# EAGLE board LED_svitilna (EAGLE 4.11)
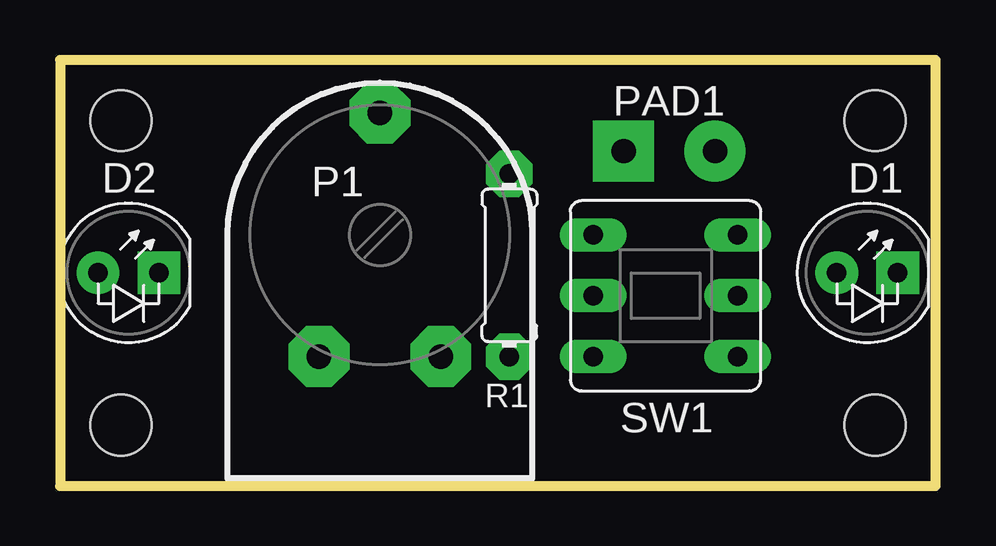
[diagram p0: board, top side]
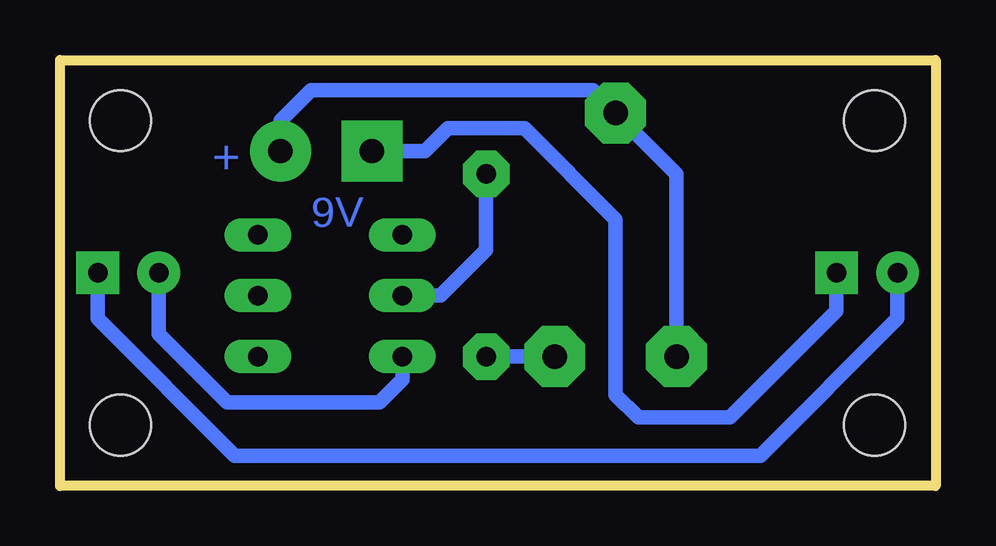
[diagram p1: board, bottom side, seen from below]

Size 36.5 x 17.77 mm. Coordinates in mm from the lower left corner, seen from the top.
Outline: 0,0 36.5,0 36.5,17.77 0,17.77 0,0
Copper layers (1*16): Top 0.035mm / dielectric 1.5mm / Bottom 0.035mm
Design rules "default": minimum track width 10mil, minimum drill 24mil, track to track 8mil, track to pad 8mil, pad to pad 8mil, via to via 8mil, smd to smd 8mil, copper to edge 40mil, drill to drill 8mil, minimum pad ring 10mil, minimum via ring 8mil, stop-mask expansion 4mil, vias tented up to drill 0mil, thermal gap 10mil
Holes 2.54 mm at 2.54,15.24 2.54,2.54 33.97,2.54 33.97,15.24

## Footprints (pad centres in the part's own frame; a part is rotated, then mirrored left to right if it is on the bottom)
LED_5 = drill 0.813 pad 1.778 round: A -1.27,0 | drill 0.813 pad 1.778 square: K 1.27,0
TP012 = drill 1.016 pad 2.54 octagon: 1 -2.54,-5.08; 2 0,5.08; 3 2.54,-5.08
PAD_2+- = drill 1.016 pad 2.54 round: + -1.905,0 | drill 1.016 pad 2.54 square: - 1.905,0
R-7,5 = drill 0.813 pad 1.93 octagon: 1 -3.81,0; 2 3.81,0
P-B170 = drill 0.813 pad 1.4 long: 1 0,5.08; 2 0,2.54; 3 0,0; 4 6.032,0; 5 6.032,2.54; 6 6.032,5.08

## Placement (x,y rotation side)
D1  LED_5  [LED_5]  33.66,8.89 0 top
D2  LED_5  [LED_5]  2.86,8.89 0 top
P1  [TP012]  13.34,10.48 0 top
PAD1  PAD_2+-  [PAD_2+-]  25.4,13.97 180 top
R1  [R-7,5]  18.73,9.21 270 top
SW1  P-B170  [P-B170]  22.23,5.4 0 top

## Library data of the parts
D1 D2 P1 PAD1 R1 SW1 = #PaJa_14

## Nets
N$1: P1.1 P1.2 PAD1.+
N$2: P1.3 R1.2
N$5: D1.K D2.A
N$6: D2.K PAD1.-
S$1: R1.1 SW1.2
S$2: D1.A SW1.3

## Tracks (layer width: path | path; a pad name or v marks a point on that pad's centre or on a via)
N$1
  Bottom 0.61: P1.1 10.79,13.02 P1.2 14.29,16.51 26.04,16.51 27.3,15.24 PAD1.+
N$2
  Bottom 0.61: P1.3 R1.2
N$5
  Bottom 0.61: D1.K 34.92,6.99 29.21,1.27 7.3,1.27 1.59,6.99 D2.A
N$6
  Bottom 0.61: PAD1.- 21.27,13.97 20.32,14.92 17.14,14.92 13.34,11.11 13.34,3.81 12.38,2.86 8.57,2.86 4.13,7.3 D2.K
S$1
  Bottom 0.61: SW1.2 20.64,7.94 18.73,9.84 R1.1
S$2
  Bottom 0.61: D1.A 32.38,6.35 29.53,3.49 23.18,3.49 22.23,4.45 SW1.3

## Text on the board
Bottom: + | 9V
